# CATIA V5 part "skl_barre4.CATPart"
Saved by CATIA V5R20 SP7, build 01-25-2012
Part number: skl_barre4
Publications: "axe_pivot_4_2", "axe_pivot_4_5", "PointE", "PointF", "PlanRef"
Bounding box of the stored display mesh (mm): x 0 to 20, y -0.087 to 85.111, z 106.172 to 323.037
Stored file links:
  U:\Projet IAO\omeyer\Catia\skl_barre4.CATPart
  U:\Projet IAO\omeyer\Catia\skl_748.CATProduct
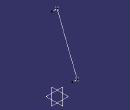
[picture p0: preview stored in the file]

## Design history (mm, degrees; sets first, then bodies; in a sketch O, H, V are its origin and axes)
Set1
  DatumPoint1 "PointE": linked copy from another document
  DatumPoint2 "PointF": linked copy from another document
  Plane1 "PlanRef": linked copy from another document
Set2
  Line1: type PtPt, FirstPoint DatumPoint1, SecondPoint DatumPoint2
  Line2 "axe_pivot_4_2": type Normal, RefPoint DatumPoint1, RefSkin Plane1, Start 0, End 20
  Line3 "axe_pivot_4_5": type Normal, RefPoint DatumPoint2, RefSkin Plane1, Start 0, End 20
Body1 (main body)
